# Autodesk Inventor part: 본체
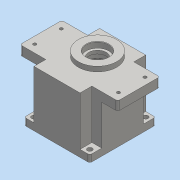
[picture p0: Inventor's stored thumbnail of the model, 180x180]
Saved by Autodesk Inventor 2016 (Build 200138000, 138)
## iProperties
Created: 2020-08
Part Number: 본체
Material: 일반
Document SubType Name: Modeling
Designer: User
Density: 1 g/cm^3
Appearance: 기본값
Author: User
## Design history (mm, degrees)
sketch "스케치1"
  geometry: L1 (-70, 30)-(70, 30); L2 (70, 30)-(70, -30); L3 (70, -30)-(-70, -30); L4 (-70, -30)-(-70, 30); L5 (-70, 30)-(70, -30); L6 (70, 30)-(-70, -30); L7 (-33, 47)-(33, 47); L8 (33, 47)-(33, -47); L9 (33, -47)-(-33, -47); L10 (-33, -47)-(-33, 47); L11 (-33, 47)-(33, -47); L12 (33, 47)-(-33, -47); 1 further point
  constraints: 24 end point, 4 midpoint, 4 parallel, 2 horizontal, 2 perpendicular
  dimensions: "d0" = 140 distance of L2.end L3.end; "d1" = 60 distance of L1.end L2.end; "d2" = 66 distance of L8.end L9.end; "d3" = 94 distance of L7.end L8.end
extrude "돌출1" new body sketch "스케치1" distance "d4" = 80; taper "d5" = 0 deg
sketch "스케치2"
  geometry: C1 r 27.5 at (0, 11); 1 further point
  constraints: 1 centre point, 1 vertical alignment
  dimensions: "d6" = 55 diameter of C1; "d7" = 11 distance of point (0, 0) C1.centre
extrude "돌출2" join sketch "스케치2" distance "d8" = 7; taper "d9" = 0 deg
hole "구멍1" diameter "d12" = 32; stored, may be unused: countersink angle "d16" = 90 deg, drill point angle "d18" = 0 deg; dims "d13" = 6, "d14" = 4, "d15" = 2, "d17" = 8.3, "d40" = 10, "d41" = 10
hole "구멍2" diameter "d21" = 25; stored, may be unused: countersink angle "d25" = 90 deg, drill point angle "d27" = 0 deg; dims "d22" = 6, "d23" = 4, "d24" = 2, "d26" = 13, "d38" = 10, "d39" = 10
sketch "스케치4"
  geometry: L1 (47, 47)-(-47, 47); L2 (-47, 47)-(-47, -47); L3 (-47, -47)-(47, -47); L4 (47, -47)-(47, 47); L5 (47, 47)-(-47, -47); L6 (-47, 47)-(47, -47); 1 further point
  constraints: 12 end point, 2 midpoint, 2 parallel, 1 horizontal, 1 perpendicular
  dimensions: "d28" = 94 distance of L3.end L2.end; "d29" = 94 distance of L2.end L1.end
extrude "돌출3" join sketch "스케치4" distance "d30" = 10; taper "d31" = 0 deg
sketch "스케치5"
  geometry: C1 r 43 at (0, 0); 1 further point
  constraints: 1 centre point, 1 coincident
  dimensions: "d32" = 86 diameter of C1
extrude "돌출4" cut sketch "스케치5" distance "d33" = 9; taper "d34" = 0 deg
sketch "스케치6"
  geometry: C1 r 40 at (0, 0); 1 further point
  constraints: 1 centre point, 1 coincident
  dimensions: "d35" = 80 diameter of C1
extrude "돌출5" cut sketch "스케치6" distance "d36" = 71; taper "d37" = 0 deg
sketch "스케치7"
  geometry: C1 r 21 at (0, 11); C2 r 15 at (0, -20); 1 further point
  constraints: 2 centre point, 2 vertical alignment
  dimensions: "d42" = 42 diameter of C1; "d44" = 11 distance of point (0, 0) C1.centre; "d45" = 30 diameter of C2; "d46" = 20 distance of point (0, 0) C2.centre
extrude "돌출6" join sketch "스케치7" distance "d47" = 7; taper "d48" = 0 deg
hole "구멍3" diameter "d51" = 35; stored, may be unused: countersink angle "d55" = 90 deg, drill point angle "d57" = 0 deg; dims "d49" = 10, "d50" = 10, "d52" = 6, "d53" = 4, "d54" = 2, "d56" = 10
hole "구멍4" diameter "d60" = 22; stored, may be unused: countersink angle "d64" = 90 deg, drill point angle "d66" = 0 deg; dims "d61" = 6, "d62" = 4, "d63" = 2, "d65" = 7, "d145" = 10, "d146" = 10
hole "구멍5" diameter "d69" = 19; stored, may be unused: countersink angle "d73" = 90 deg, drill point angle "d75" = 0 deg; dims "d70" = 6, "d71" = 4, "d72" = 2, "d74" = 10, "d143" = 10, "d144" = 10
sketch "스케치9"
  geometry: L1 (-47, 47)-(47, 47); L2 (47, 47)-(47, -47); L3 (47, -47)-(-47, -47); L4 (-47, -47)-(-47, 47); L5 (-47, 47)-(47, -47); L6 (47, 47)-(-47, -47); L7 (-100, 100)-(100, 100); L8 (100, 100)-(100, -100); L9 (100, -100)-(-100, -100); L10 (-100, -100)-(-100, 100); L11 (-100, 100)-(100, -100); L12 (100, 100)-(-100, -100); 1 further point
  constraints: 24 end point, 4 midpoint, 4 parallel, 2 horizontal, 2 perpendicular, 1 point on line
  dimensions: "d76" = 94 distance of L2.end L3.end; "d77" = 94 distance of L1.end L2.end; "d78" = 200 distance of L8.end L9.end
extrude "돌출7" cut sketch "스케치9" distance "d79" = 67; taper "d80" = 0 deg
sketch "스케치10"
  geometry: 2 further points
  dimensions: "d81" = 40 horizontal distance of point (0, 0) point (-40, 40); "d82" = 40 horizontal distance of point (0, 0) point (-40, 40)
hole "구멍6" sketch "스케치10" at (-40, 40) diameter "d83" = 7; stored, may be unused: countersink angle "d87" = 90 deg, drill point angle "d89" = 0 deg; dims "d84" = 6, "d85" = 4, "d86" = 2, "d88" = 10
sketch "스케치12"
  geometry: 2 further points
  dimensions: "d96" = 60 horizontal distance of point (0, 0) point (60, 19); "d97" = 19 vertical distance of point (0, 0) point (60, 19)
hole "구멍7" sketch "스케치12" at (60, 19) diameter "d98" = 4.5; stored, may be unused: countersink angle "d102" = 90 deg, drill point angle "d104" = 0 deg; dims "d99" = 6, "d100" = 10, "d101" = 5, "d103" = 13
sketch "스케치13"
  geometry: A1 r 21 centre (0, 11) between (8.978, -7.984) and (-8.978, -7.984) reference; A2 r 15 centre (0, -20) between (-8.978, -7.984) and (8.978, -7.984) reference; A3 r 40 centre (0, 0) between (39.279, 7.559) and (39.279, -7.559) reference; A4 r 4 centre (36, 0) between (36.19, 3.995) and (36.19, -3.995); A5 r 36 centre (0, 0) between (36, 0) and (35.772, 4.045); A6 r 3 centre (36.333, 6.992) between (35.772, 4.045) and (39.279, 7.559); A7 r 3 centre (36.333, -6.992) between (39.279, -7.559) and (35.772, -4.045); 1 further point
  constraints: 13 point on circle, 4 centre point, 4 tangent, 1 coincident, 1 horizontal alignment
  dimensions: "d111" = 8 diameter of A4; "d112" = 72 diameter of A5; "d113" = 6 diameter of A6; "d114" = 6 diameter of A7
extrude "돌출8" join sketch "스케치13" distance "d115" = 62; taper "d116" = 0 deg
hole "구멍8" diameter "d119" = 3.242; stored, may be unused: countersink angle "d123" = 90 deg, drill point angle "d125" = 118 deg; dims "d117" = 10, "d118" = 10, "d120" = 7, "d121" = 10, "d122" = 5, "d124" = 9
chamfer "모따기1" distance "d126" = 0.8; stored, may be unused: second distance "d127" = 2, angle "d128" = 30 deg
chamfer "모따기2" distance "d129" = 1; stored, may be unused: second distance "d130" = 2, angle "d131" = 30 deg
chamfer "모따기3" distance "d132" = 1; stored, may be unused: second distance "d133" = 2, angle "d134" = 30 deg
fillet "모깎기1" dims "d135" = 3
fillet "모깎기2" dims "d136" = 3
fillet "모깎기3" dims "d137" = 3
sketch "스케치14"
  geometry: L1 (-11, 80)-(77, 80) reference; L2 (0, 0)-(66, 0) reference; 3 further points
  constraints: 1 midpoint, 1 vertical alignment, 1 other
  dimensions: "d138" = 40 distance from line of point (33, 40) L1
feature "엠보싱1" sketch "스케치14" dims "d0" = 140, "d1" = 60, "d23" = 4, "d139" = 0.5, "d140" = 0
node "솔리드1"
pattern_linear "직사각형 패턴1" dims "d92" = 80
pattern_linear "직사각형 패턴2" dims "d107" = 120, "d110" = 38
mirror "대칭1"
node "투영된 루프1"
